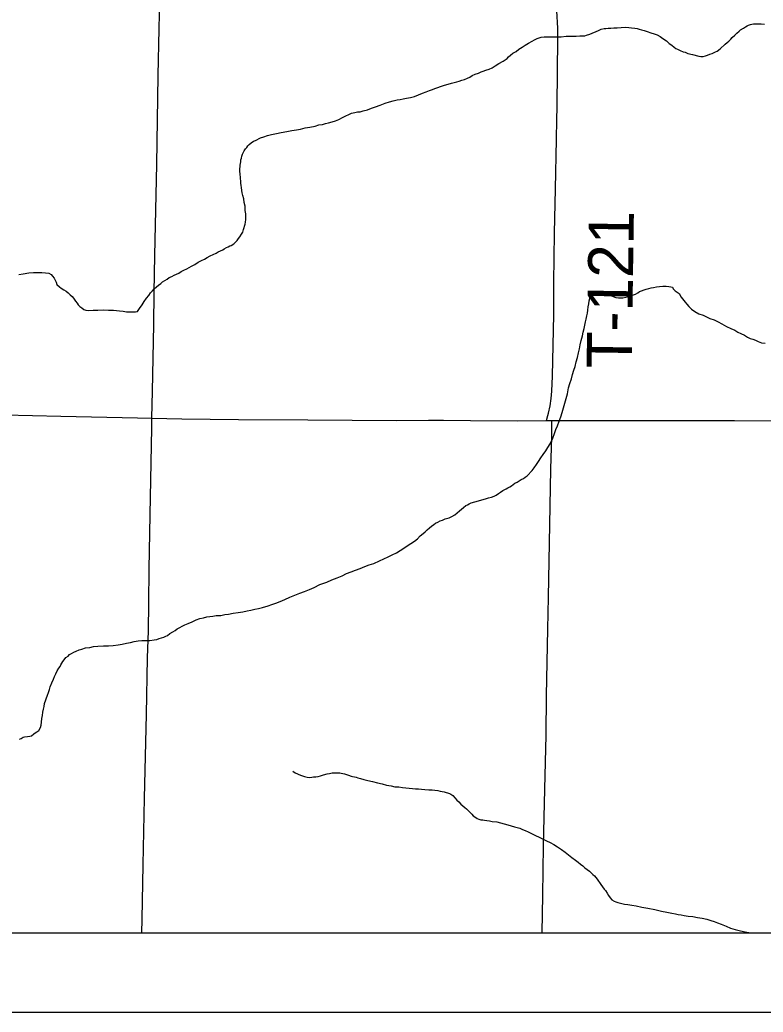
# Model space of a CAD drawing. Extents: x 0 to 64.8, y -5 to 22.
# Drawn here: x 6.488 to 7.424, y 14 to 15.251 of the extents above; entities that cross this region are included whole.
import ezdxf

# ---------------------------------------------------------------- set-up
doc = ezdxf.new("R2010")
doc.units = 0
for name, color, linetype in [('GM_X_Adjacent_County', 7, 'Continuous'), ('GM_X_County', 7, 'Continuous'), ('GM_X_Minor_River', 7, 'Continuous'), ('GM_X_Township', 7, 'Continuous'), ('GM_X_Township_Road', 7, 'Continuous'), ('GM_X_Township_Road_Text', 7, 'Continuous'), ('SH_Data', 7, 'Continuous')]:
    doc.layers.add(name, color=color, linetype=linetype)

msp = doc.modelspace()

# ---------------------------------------------------------------- linework, layer by layer
at = {"layer": 'GM_X_Adjacent_County'}
msp.add_lwpolyline([(2.1, 19.9176), (2.1, 14.1), (8.9, 14.1), (8.9, 19.781)], dxfattribs=at)
at = {"layer": 'GM_X_County'}
msp.add_lwpolyline([(2.1, 19.9176), (2.1, 14.1), (8.9, 14.1), (8.9, 19.781)], dxfattribs=at)
at = {"layer": 'GM_X_Minor_River'}
for points in [[(7.0383, 15.1728), (7.0414, 15.1735), (7.0448, 15.1746), (7.0479, 15.1757), (7.0517, 15.1771), (7.0548, 15.1785), (7.0579, 15.1804), (7.0617, 15.1822), (7.0656, 15.1836), (7.069, 15.1851), (7.0717, 15.1861), (7.0748, 15.1872), (7.079, 15.1886), (7.0828, 15.1904), (7.0867, 15.1926), (7.0913, 15.1959), (7.0967, 15.1985), (7.0994, 15.2003), (7.1017, 15.2022), (7.1037, 15.204), (7.106, 15.2062), (7.1091, 15.2088), (7.113, 15.211), (7.1165, 15.2136), (7.1207, 15.2162), (7.1246, 15.2187), (7.1288, 15.2213), (7.1334, 15.2239), (7.1365, 15.2257), (7.1396, 15.2271), (7.1423, 15.2282), (7.1446, 15.2289), (7.1484, 15.2292), (7.1518, 15.2291), (7.156, 15.2294), (7.1605, 15.2293), (7.1655, 15.2292), (7.17, 15.2295), (7.1761, 15.2301), (7.1803, 15.23), (7.1845, 15.2303), (7.1887, 15.2302), (7.1933, 15.2305), (7.1967, 15.2304), (7.1997, 15.2307), (7.202, 15.2314), (7.2059, 15.2325), (7.217, 15.2375), (7.2204, 15.239), (7.2239, 15.2397), (7.2262, 15.24), (7.2292, 15.2403), (7.2326, 15.2402), (7.2361, 15.2405), (7.2403, 15.2408), (7.2456, 15.2411), (7.2505, 15.2413), (7.2551, 15.2412), (7.2585, 15.2408), (7.2627, 15.2403), (7.2657, 15.2399), (7.2684, 15.239), (7.271, 15.2382), (7.2744, 15.2374), (7.2782, 15.2362), (7.2827, 15.2345), (7.2869, 15.2333), (7.291, 15.2317), (7.2948, 15.2297), (7.2981, 15.2274), (7.3026, 15.2242), (7.306, 15.2211), (7.3093, 15.2187), (7.3123, 15.2164), (7.3146, 15.2148), (7.3164, 15.2137), (7.3198, 15.2121), (7.3236, 15.2105), (7.3262, 15.21), (7.3296, 15.2084), (7.3353, 15.2071), (7.3436, 15.2051), (7.3459, 15.2046), (7.3489, 15.2046), (7.3516, 15.2053), (7.3543, 15.2063), (7.3574, 15.2074), (7.3604, 15.2085), (7.3643, 15.2103), (7.3666, 15.2114), (7.3701, 15.214), (7.3767, 15.2199), (7.379, 15.2221), (7.3813, 15.224), (7.3836, 15.2262), (7.3856, 15.2284), (7.3887, 15.2314), (7.3914, 15.234), (7.3942, 15.2366), (7.3961, 15.2381), (7.3996, 15.2403)], [(7.3996, 15.2403), (7.4023, 15.2421), (7.4042, 15.2432), (7.4061, 15.2439), (7.4084, 15.245), (7.4103, 15.2453), (7.4122, 15.2457), (7.4149, 15.2456), (7.4187, 15.2455), (7.4221, 15.2455), (7.4263, 15.2454)], [(6.7542, 14.9665), (6.7573, 14.9684), (6.76, 14.971), (6.7616, 14.9728), (6.7635, 14.9751), (6.7651, 14.9773), (6.7671, 14.9807), (6.7686, 14.9833), (6.7698, 14.9863), (6.7719, 14.9931), (6.7723, 14.9958), (6.7724, 14.9992), (6.7725, 15.0026), (6.7726, 15.0064), (6.7719, 15.0106), (6.7717, 15.0159), (6.7706, 15.0205), (6.77, 15.0251), (6.7689, 15.0293), (6.7679, 15.0327), (6.7676, 15.0358), (6.7669, 15.0392), (6.7666, 15.0419), (6.7662, 15.0449), (6.7663, 15.0476), (6.766, 15.0506), (6.7657, 15.0529), (6.7653, 15.0552), (6.7654, 15.0571), (6.765, 15.059), (6.7651, 15.0632), (6.7656, 15.0654), (6.7656, 15.0677), (6.7657, 15.0696), (6.7661, 15.0719), (6.7661, 15.0741), (6.767, 15.0764), (6.7674, 15.0791), (6.7682, 15.0813), (6.769, 15.0832), (6.7706, 15.0858), (6.7722, 15.0881), (6.7737, 15.0899), (6.7749, 15.0918), (6.7769, 15.0937), (6.7792, 15.0955), (6.7823, 15.0977), (6.7846, 15.0988), (6.7911, 15.1021), (6.7953, 15.1031), (6.7999, 15.1049), (6.8049, 15.1063), (6.811, 15.1073), (6.8171, 15.1087), (6.824, 15.1101), (6.8305, 15.1111), (6.8362, 15.1121), (6.8416, 15.1131), (6.8473, 15.1145), (6.853, 15.1155), (6.8599, 15.1169), (6.8645, 15.1183), (6.8691, 15.1189), (6.8729, 15.12), (6.8767, 15.121), (6.8813, 15.1221), (6.8855, 15.1235), (6.8897, 15.1253), (6.8943, 15.1275), (6.8986, 15.1296), (6.9024, 15.1315), (6.9059, 15.1333), (6.9101, 15.1339), (6.9131, 15.1346), (6.9166, 15.1349), (6.9204, 15.136), (6.9258, 15.1374), (6.9307, 15.1392), (6.9361, 15.141), (6.9419, 15.1431), (6.948, 15.1456), (6.9537, 15.1474), (6.9583, 15.1488), (6.9633, 15.1498), (6.9671, 15.1505), (6.9709, 15.1512), (6.9751, 15.1519), (6.9801, 15.1529), (6.9851, 15.1543), (6.9901, 15.1561), (6.995, 15.1582), (6.9996, 15.16), (7.0039, 15.1615), (7.0077, 15.1629), (7.0108, 15.164), (7.0146, 15.1654), (7.0177, 15.1668), (7.0215, 15.1679), (7.0315, 15.1711), (7.0349, 15.1718), (7.0383, 15.1728)], [(6.4864, 14.9297), (6.4918, 14.9307), (6.499, 14.9317), (6.5048, 14.9323), (6.5101, 14.9322), (6.5154, 14.9324), (6.52, 14.932), (6.5241, 14.9315), (6.5271, 14.9299), (6.529, 14.9276), (6.5308, 14.9253), (6.5323, 14.9226), (6.5334, 14.9199), (6.5344, 14.9172), (6.5378, 14.9141), (6.54, 14.9125), (6.543, 14.9105), (6.546, 14.9086), (6.5487, 14.9066), (6.5513, 14.9043), (6.5535, 14.902), (6.5553, 14.9), (6.5579, 14.8962), (6.5598, 14.8935), (6.5612, 14.8915), (6.5635, 14.8896), (6.5657, 14.8876), (6.5683, 14.8857), (6.571, 14.8848), (6.5748, 14.8844), (6.5801, 14.8846), (6.5862, 14.8849), (6.593, 14.8851), (6.5995, 14.885), (6.6056, 14.8848), (6.6132, 14.8839), (6.6181, 14.8834), (6.6223, 14.8829), (6.6261, 14.8828), (6.6302, 14.8827), (6.6337, 14.8827), (6.6359, 14.883), (6.6387, 14.8871), (6.6418, 14.8916), (6.6446, 14.8957), (6.6474, 14.8998), (6.6501, 14.9032), (6.6524, 14.9066), (6.6548, 14.9092), (6.6571, 14.9118), (6.6598, 14.914), (6.6626, 14.9162), (6.6653, 14.9184), (6.6676, 14.9203), (6.6703, 14.9221), (6.6734, 14.9239), (6.6761, 14.9258), (6.6792, 14.9272), (6.6822, 14.9291), (6.6853, 14.9301), (6.688, 14.9316), (6.6911, 14.9334), (6.6945, 14.9352), (6.698, 14.9367), (6.7011, 14.9385), (6.7042, 14.9403), (6.7084, 14.9425), (6.7123, 14.9451), (6.7165, 14.9473), (6.7203, 14.9491), (6.7238, 14.9513), (6.7277, 14.9531), (6.7315, 14.9549), (6.735, 14.9567), (6.7377, 14.9582), (6.7407, 14.9596), (6.7434, 14.9607), (6.7453, 14.9622), (6.748, 14.9636), (6.7503, 14.9647), (6.7523, 14.9658), (6.7542, 14.9665)], [(7.0517, 14.6396), (7.054, 14.6407), (7.0567, 14.6418), (7.0613, 14.6432), (7.0659, 14.6446), (7.0701, 14.6457), (7.0747, 14.6471), (7.0785, 14.6481), (7.0823, 14.6492), (7.0854, 14.6503), (7.0881, 14.6517), (7.0908, 14.6536), (7.0935, 14.6554), (7.0966, 14.6576), (7.1004, 14.6594), (7.1027, 14.6609), (7.1054, 14.6623), (7.1074, 14.6634), (7.1093, 14.6649), (7.1116, 14.6668), (7.1143, 14.6682), (7.117, 14.6697), (7.1197, 14.6715), (7.1224, 14.6726), (7.1247, 14.6741), (7.127, 14.6759), (7.1333, 14.6826), (7.136, 14.686), (7.1388, 14.6901), (7.1415, 14.6942), (7.1443, 14.6987), (7.1474, 14.7028), (7.1506, 14.7073), (7.1533, 14.7118), (7.1561, 14.7163), (7.1593, 14.7234), (7.1613, 14.7294), (7.1633, 14.7343), (7.1653, 14.7392), (7.1674, 14.7449), (7.1694, 14.7505), (7.171, 14.7558), (7.1727, 14.7615), (7.1744, 14.7675), (7.176, 14.7736), (7.1777, 14.7792), (7.179, 14.7868), (7.181, 14.7924), (7.183, 14.7981), (7.1843, 14.8038), (7.1859, 14.809), (7.1876, 14.8139), (7.1888, 14.8196), (7.1905, 14.8253), (7.1918, 14.8309), (7.193, 14.8362), (7.1939, 14.8411), (7.1952, 14.8464), (7.1968, 14.8525), (7.1977, 14.857), (7.1989, 14.8615), (7.1998, 14.8657), (7.2006, 14.8699), (7.2015, 14.8736), (7.2023, 14.8778), (7.2032, 14.8812), (7.2036, 14.885), (7.2041, 14.8892), (7.2046, 14.8926), (7.205, 14.8964), (7.2059, 14.8994), (7.2063, 14.9024), (7.2071, 14.9047), (7.2091, 14.9069), (7.2121, 14.908), (7.214, 14.9075), (7.2167, 14.9071), (7.2193, 14.9067), (7.222, 14.9062), (7.2243, 14.9058), (7.2269, 14.905), (7.2296, 14.9042), (7.2326, 14.9033), (7.2356, 14.9021), (7.239, 14.9009), (7.242, 14.9005), (7.2451, 14.9004), (7.2477, 14.9003), (7.2512, 14.901), (7.2546, 14.9021), (7.258, 14.9031), (7.2611, 14.9042), (7.2634, 14.9049), (7.2665, 14.9067), (7.2688, 14.9082), (7.2711, 14.9093), (7.2746, 14.9104), (7.2772, 14.9114), (7.2803, 14.9121), (7.2834, 14.9128), (7.2864, 14.9135)], [(7.2864, 14.9135), (7.2902, 14.9142), (7.294, 14.9145), (7.2982, 14.9151), (7.3024, 14.915), (7.3054, 14.9146), (7.3081, 14.9142), (7.31, 14.9137), (7.3111, 14.9118), (7.3137, 14.9091), (7.3159, 14.9075), (7.3186, 14.9056), (7.3211, 14.9013), (7.3263, 14.8948), (7.3281, 14.8924), (7.3307, 14.8893), (7.3341, 14.8862), (7.3382, 14.8831), (7.3434, 14.8803), (7.3487, 14.8783), (7.3532, 14.8763), (7.3574, 14.8743), (7.3627, 14.8727), (7.3676, 14.8703), (7.3724, 14.8675), (7.3781, 14.8643), (7.3837, 14.8616), (7.3886, 14.8595), (7.3924, 14.8572), (7.3965, 14.8552), (7.401, 14.8532), (7.4048, 14.8508), (7.4081, 14.8492), (7.4115, 14.8484), (7.4149, 14.8468), (7.4183, 14.8452), (7.4225, 14.8436), (7.427, 14.8431)], [(6.5704, 14.4591), (6.5758, 14.4597), (6.5807, 14.4607), (6.5861, 14.4614), (6.5933, 14.4616), (6.5994, 14.4618), (6.6055, 14.4621), (6.6116, 14.4631), (6.6169, 14.4637), (6.6223, 14.4651), (6.6272, 14.4661), (6.6318, 14.4672), (6.6368, 14.4682), (6.6414, 14.4685), (6.6467, 14.4683), (6.6516, 14.4686), (6.657, 14.4693), (6.6604, 14.4699), (6.6635, 14.471), (6.6661, 14.4717), (6.6692, 14.4728), (6.6719, 14.4739), (6.6738, 14.4749), (6.6769, 14.4772), (6.6804, 14.4794), (6.6835, 14.4812), (6.6862, 14.483), (6.6958, 14.4881), (6.7, 14.4899), (6.705, 14.4921), (6.71, 14.4943), (6.7146, 14.4961), (6.7192, 14.4971), (6.7234, 14.4981), (6.7272, 14.4988), (6.731, 14.4991), (6.7352, 14.4998), (6.7409, 14.5), (6.7459, 14.501), (6.7509, 14.5017), (6.7566, 14.5027), (6.7627, 14.5037), (6.7688, 14.5047), (6.7741, 14.5057), (6.7787, 14.5068), (6.7837, 14.5078), (6.7887, 14.5088), (6.7936, 14.5102), (6.8005, 14.512), (6.8051, 14.5138), (6.8105, 14.5155), (6.8159, 14.5177), (6.8216, 14.5202), (6.8278, 14.5231), (6.8343, 14.5256), (6.8404, 14.5282), (6.8466, 14.5303), (6.8527, 14.5328), (6.8588, 14.5353), (6.8658, 14.539), (6.8746, 14.5418), (6.8811, 14.5447), (6.8876, 14.5476), (6.8938, 14.5501), (6.8995, 14.5527), (6.9053, 14.5548), (6.9107, 14.557), (6.9168, 14.5591), (6.9225, 14.5616), (6.9279, 14.5638), (6.9337, 14.5656), (6.941, 14.5688), (6.9463, 14.5713), (6.9517, 14.5739), (6.9571, 14.5764), (6.9625, 14.579), (6.9671, 14.5819), (6.9806, 14.5907), (6.9849, 14.5936), (6.9887, 14.5966), (6.9922, 14.6003), (6.9961, 14.6033), (6.9984, 14.6055), (7.0012, 14.6081), (7.0039, 14.6103), (7.0066, 14.6125), (7.0093, 14.6147), (7.0116, 14.6162), (7.0143, 14.6177), (7.0174, 14.6191), (7.0204, 14.6202), (7.0239, 14.6216), (7.0289, 14.623), (7.0323, 14.6249), (7.0358, 14.6267), (7.0389, 14.6293), (7.0416, 14.6319), (7.0443, 14.6341), (7.0467, 14.6359), (7.0498, 14.6385), (7.0517, 14.6396)], [(6.4872, 14.3439), (6.4895, 14.345), (6.4918, 14.3465), (6.4938, 14.3472), (6.4976, 14.3475), (6.5002, 14.3478), (6.5025, 14.3482), (6.5052, 14.3508), (6.5072, 14.3522), (6.5091, 14.3533), (6.5118, 14.3552), (6.5138, 14.3589), (6.5146, 14.3619), (6.5151, 14.3653), (6.5156, 14.3703), (6.5164, 14.3741), (6.5169, 14.3782), (6.5174, 14.382), (6.5182, 14.3854), (6.519, 14.3892), (6.5227, 14.3994), (6.5239, 14.4031), (6.5251, 14.4065), (6.526, 14.4099), (6.528, 14.4152), (6.53, 14.4197), (6.5316, 14.4231), (6.5332, 14.4265), (6.5348, 14.4302), (6.5368, 14.4336), (6.5387, 14.4358), (6.5395, 14.4377), (6.5407, 14.44), (6.5419, 14.4419), (6.5435, 14.4441), (6.5458, 14.4471), (6.5485, 14.4489), (6.5505, 14.4508), (6.5528, 14.4522), (6.5559, 14.4537), (6.5589, 14.4551), (6.5624, 14.4566), (6.5658, 14.4576), (6.5704, 14.4591)], [(6.8319, 14.3039), (6.8349, 14.3015), (6.8413, 14.2987), (6.8466, 14.2971), (6.85, 14.2962), (6.8523, 14.2958), (6.8557, 14.2961), (6.858, 14.2964), (6.8607, 14.2968), (6.8637, 14.2971), (6.8668, 14.2978), (6.8702, 14.2992), (6.8752, 14.3002), (6.8779, 14.3009), (6.8813, 14.3016), (6.8908, 14.3018), (6.8927, 14.3013), (6.8946, 14.3009), (6.8969, 14.3005), (6.8995, 14.2997), (6.9021, 14.2989), (6.9052, 14.2976), (6.907, 14.2972), (6.9093, 14.2964), (6.9116, 14.296), (6.9138, 14.2952), (6.9172, 14.2943), (6.9214, 14.2931), (6.9263, 14.2919), (6.932, 14.2906), (6.9384, 14.2889), (6.9445, 14.2876), (6.9498, 14.286), (6.9558, 14.2851), (6.9604, 14.2842), (6.9653, 14.2838), (6.9698, 14.2833), (6.974, 14.2828), (6.9782, 14.2823), (6.9824, 14.2818), (6.9862, 14.2814), (6.9903, 14.2813), (6.9941, 14.2812), (6.9983, 14.2807), (7.0032, 14.2802), (7.0074, 14.2801), (7.0108, 14.2797), (7.0146, 14.2792), (7.0176, 14.2784), (7.0199, 14.278), (7.0226, 14.2775), (7.0248, 14.2767), (7.0267, 14.2763), (7.029, 14.2755), (7.0309, 14.2747), (7.0335, 14.2731), (7.0365, 14.2696), (7.0383, 14.2673), (7.0409, 14.265), (7.0435, 14.2622), (7.0461, 14.2599), (7.0484, 14.2579), (7.0506, 14.2564), (7.0573, 14.2494), (7.0591, 14.2474), (7.061, 14.2463), (7.064, 14.2439), (7.0663, 14.2431), (7.0685, 14.2423), (7.0712, 14.2422), (7.0735, 14.2418), (7.0761, 14.2414), (7.0795, 14.2413), (7.0829, 14.2404), (7.089, 14.2399), (7.0935, 14.2387), (7.0981, 14.2374), (7.1026, 14.2362), (7.1071, 14.235), (7.1109, 14.2337), (7.1143, 14.2329), (7.1177, 14.2317), (7.1211, 14.2301), (7.1245, 14.2289), (7.1283, 14.2273), (7.1335, 14.2249), (7.1377, 14.2225), (7.1422, 14.2205), (7.1471, 14.2181), (7.1516, 14.2161), (7.1561, 14.2137), (7.1606, 14.2113), (7.1651, 14.2082), (7.1703, 14.205), (7.1748, 14.2015), (7.1793, 14.1984), (7.1834, 14.1949), (7.1879, 14.1917), (7.1913, 14.189), (7.1943, 14.1867), (7.1972, 14.1843)], [(7.1972, 14.1843), (7.1999, 14.182), (7.2025, 14.18), (7.2055, 14.1777), (7.2077, 14.1757), (7.2099, 14.1734), (7.2118, 14.1718), (7.2151, 14.1676), (7.217, 14.1653), (7.2184, 14.1633), (7.2199, 14.161), (7.2243, 14.1552), (7.2258, 14.1533), (7.228, 14.1498), (7.2295, 14.1471), (7.2317, 14.144), (7.2339, 14.1417), (7.2365, 14.1397), (7.2388, 14.1389), (7.2414, 14.1381), (7.2445, 14.1373), (7.2498, 14.136), (7.2539, 14.1355), (7.2589, 14.1347), (7.2645, 14.1338), (7.2714, 14.1325), (7.2793, 14.1312), (7.288, 14.1295), (7.2963, 14.1274), (7.3031, 14.1261), (7.3092, 14.1248), (7.3141, 14.1239), (7.3175, 14.1231), (7.3213, 14.1226), (7.3251, 14.1218), (7.33, 14.1209), (7.3357, 14.1204), (7.3418, 14.1195), (7.3478, 14.1186), (7.3535, 14.117), (7.3584, 14.1157), (7.3626, 14.1141), (7.3671, 14.1125), (7.3716, 14.1109), (7.378, 14.1084), (7.3833, 14.106), (7.3893, 14.104), (7.3961, 14.1023), (7.4018, 14.1011), (7.406, 14.1002), (7.4067, 14.1)]]:
    msp.add_lwpolyline(points, dxfattribs=at)
at = {"layer": 'GM_X_Township'}
msp.add_lwpolyline([(5.5757, 14.1), (8.9, 14.1), (8.9, 19.781)], dxfattribs=at)
at = {"layer": 'GM_X_Township_Road'}
for points in [[(6.6542, 14.7486), (6.6548, 14.7825), (6.6564, 14.8664), (6.6572, 14.9069), (6.658, 14.9535), (6.6603, 15.0685), (6.6621, 15.1804), (6.6633, 15.2395), (6.6643, 15.2768), (6.6652, 15.3234), (6.6665, 15.3887), (6.6675, 15.4415), (6.6679, 15.4602), (6.6682, 15.4881), (6.6705, 15.5814), (6.6714, 15.6094), (6.6721, 15.6498), (6.6731, 15.6964), (6.6738, 15.7555), (6.6738, 15.7648), (6.6739, 15.7722)], [(7.1516, 14.7456), (7.1532, 14.7521), (7.154, 14.7551), (7.1561, 14.7642), (7.1574, 14.7734), (7.1583, 14.7827), (7.1591, 14.8014), (7.1605, 14.8792), (7.1607, 14.9196), (7.1614, 14.9819), (7.1628, 15.0379), (7.1642, 15.1001), (7.1646, 15.125), (7.1647, 15.1406), (7.1653, 15.1872), (7.1658, 15.2246), (7.1656, 15.2401), (7.1644, 15.2619)], [(6.0518, 14.7631), (6.061, 14.763), (6.12, 14.7614), (6.1511, 14.7604), (6.1822, 14.7599), (6.2786, 14.7577), (6.3687, 14.7559), (6.4682, 14.753), (6.5396, 14.7512), (6.636, 14.7491), (6.6542, 14.7486)], [(6.6497, 14.4805), (6.6497, 14.481), (6.6503, 14.5152), (6.6509, 14.5587), (6.6523, 14.6489), (6.654, 14.7359), (6.6542, 14.7486)], [(6.6542, 14.7486), (6.6919, 14.7478), (6.7635, 14.7472), (6.8505, 14.7464), (6.9624, 14.7457), (7.0028, 14.7461), (7.0215, 14.746), (7.0557, 14.7458), (7.1148, 14.7455), (7.1516, 14.7456)], [(7.1459, 14.1), (7.1468, 14.1475), (7.1478, 14.2096), (7.1493, 14.281), (7.1508, 14.3493), (7.1514, 14.399), (7.1531, 14.4828), (7.1538, 14.5232), (7.155, 14.5915), (7.1569, 14.6846), (7.158, 14.725), (7.1581, 14.7419), (7.1581, 14.7456)], [(7.1516, 14.7456), (7.1581, 14.7456)], [(7.1581, 14.7456), (7.1894, 14.7457), (7.2547, 14.7459), (7.3137, 14.7458), (7.3884, 14.7459), (7.4412, 14.7455), (7.6495, 14.7457), (7.6594, 14.7455)], [(6.6415, 14.1), (6.6418, 14.1173), (6.6431, 14.1857), (6.6448, 14.2696), (6.6473, 14.3753), (6.6485, 14.4468), (6.6497, 14.4805)]]:
    msp.add_lwpolyline(points, dxfattribs=at)
at = {"layer": 'SH_Data'}
for p, q in [((2.1, 14.1), (8.9, 14.1)), ((2, 14), (9, 14))]:
    msp.add_line(p, q, dxfattribs=at)

# ---------------------------------------------------------------- texts
at = {"layer": 'GM_X_Township_Road_Text'}
msp.add_text('T-121', height=0.05682, rotation=89.1592, dxfattribs=at).set_placement((7.2587, 14.8111))

doc.saveas('drawing.dxf')
